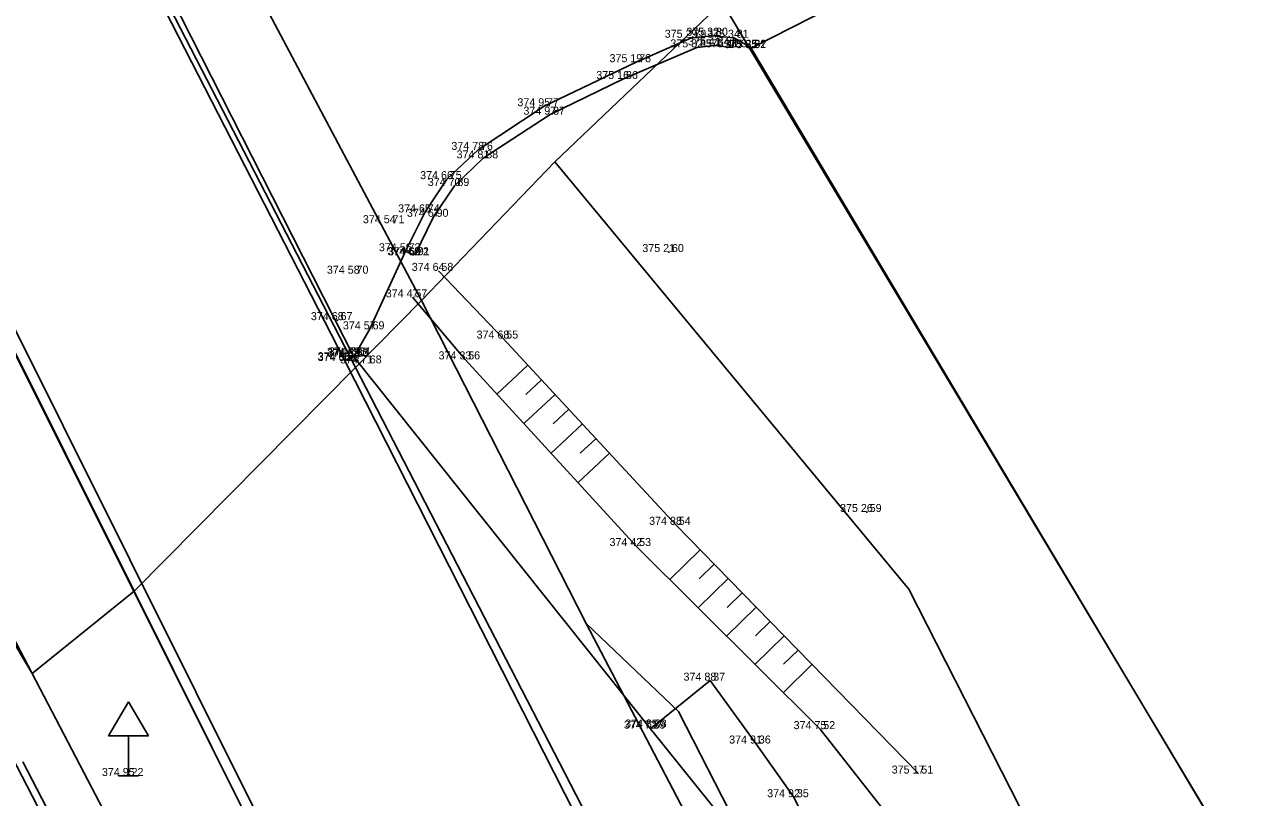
# Model space of a CAD drawing. Extents: x -601196 to -600262, y -1082523 to -1081922.
# Drawn here: x -600468.24 to -600437.88, y -1082336.09 to -1082316.78 of the extents above; entities that cross this region are included whole.
import ezdxf

# ---------------------------------------------------------------- set-up
doc = ezdxf.new("R2010")
doc.units = 0
for name, color, linetype in [('Vrstva 1', 7, 'Continuous'), ('Vrstva 10', 7, 'Continuous'), ('Vrstva 11', 7, 'Continuous'), ('Vrstva 14', 7, 'Continuous'), ('Vrstva 2', 7, 'Continuous'), ('Vrstva 20', 7, 'Continuous'), ('Vrstva 25', 7, 'Continuous'), ('Vrstva 3', 7, 'Continuous'), ('Vrstva 34', 7, 'Continuous'), ('Vrstva 47', 7, 'Continuous'), ('Vrstva 7', 7, 'Continuous')]:
    doc.layers.add(name, color=color, linetype=linetype)

msp = doc.modelspace()

# ---------------------------------------------------------------- linework, layer by layer
at = {"layer": 'Vrstva 1'}
for p, q in [((-600451.58, -1082317.12), (-600451.58, -1082317.12)), ((-600451.04, -1082317.07), (-600451.04, -1082317.07)), ((-600450.52, -1082317.12), (-600450.52, -1082317.12)), ((-600451.44, -1082317.36), (-600451.44, -1082317.36)), ((-600451, -1082317.31), (-600451, -1082317.31)), ((-600450.56, -1082317.36), (-600450.56, -1082317.36)), ((-600450.09, -1082317.38), (-600450.09, -1082317.38)), ((-600450.08, -1082317.37), (-600450.08, -1082317.37)), ((-600452.96, -1082317.73), (-600452.96, -1082317.73)), ((-600453.29, -1082318.15), (-600453.29, -1082318.15)), ((-600455.26, -1082318.83), (-600455.26, -1082318.83)), ((-600455.11, -1082319.04), (-600455.11, -1082319.04)), ((-600456.91, -1082319.92), (-600456.91, -1082319.92)), ((-600456.78, -1082320.13), (-600456.78, -1082320.13)), ((-600457.69, -1082320.65), (-600457.69, -1082320.65)), ((-600457.5, -1082320.82), (-600457.5, -1082320.82)), ((-600458.24, -1082321.48), (-600458.24, -1082321.48)), ((-600459.12, -1082321.75), (-600459.12, -1082321.75)), ((-600458.02, -1082321.59), (-600458.02, -1082321.59)), ((-600458.72, -1082322.45), (-600458.72, -1082322.45)), ((-600458.51, -1082322.55), (-600458.51, -1082322.55)), ((-600458.49, -1082322.55), (-600458.49, -1082322.55)), ((-600452.14, -1082322.47), (-600452.14, -1082322.47)), ((-600457.9, -1082322.94), (-600457.9, -1082322.94)), ((-600460.02, -1082323.01), (-600460.02, -1082323.01)), ((-600458.55, -1082323.6), (-600458.55, -1082323.6)), ((-600460.42, -1082324.17), (-600460.42, -1082324.17)), ((-600459.62, -1082324.4), (-600459.62, -1082324.4)), ((-600456.28, -1082324.63), (-600456.28, -1082324.63)), ((-600460.02, -1082325.06), (-600460.02, -1082325.06)), ((-600460.01, -1082325.09), (-600460.01, -1082325.09)), ((-600459.97, -1082325.05), (-600459.97, -1082325.05)), ((-600460.25, -1082325.17), (-600460.25, -1082325.17)), ((-600460.25, -1082325.19), (-600460.25, -1082325.19)), ((-600459.69, -1082325.25), (-600459.69, -1082325.25)), ((-600457.23, -1082325.15), (-600457.23, -1082325.15)), ((-600447.2, -1082328.96), (-600447.2, -1082328.96)), ((-600451.97, -1082329.28), (-600451.97, -1082329.28)), ((-600452.96, -1082329.81), (-600452.96, -1082329.81)), ((-600451.11, -1082333.17), (-600451.11, -1082333.17)), ((-600452.6, -1082334.37), (-600452.6, -1082334.37)), ((-600452.57, -1082334.34), (-600452.57, -1082334.34)), ((-600448.36, -1082334.38), (-600448.36, -1082334.38)), ((-600449.97, -1082334.74), (-600449.97, -1082334.74)), ((-600465.64, -1082335.55), (-600465.64, -1082335.55)), ((-600445.91, -1082335.49), (-600445.91, -1082335.49)), ((-600449.02, -1082336.08), (-600449.02, -1082336.08))]:
    msp.add_line(p, q, dxfattribs=at)
at = {"layer": 'Vrstva 10'}
for p, q in [((-600460.01, -1082325.09), (-600465.44, -1082314.41)), ((-600461.09, -1082339.77), (-600472.22, -1082317.55)), ((-600452.6, -1082334.37), (-600460.01, -1082325.09)), ((-600451.11, -1082333.17), (-600452.6, -1082334.37)), ((-600449.97, -1082334.74), (-600451.11, -1082333.17)), ((-600450.73, -1082336.7), (-600452.6, -1082334.37)), ((-600449.02, -1082336.08), (-600449.97, -1082334.74)), ((-600448.04, -1082338.04), (-600449.02, -1082336.08))]:
    msp.add_line(p, q, dxfattribs=at)
at = {"layer": 'Vrstva 11'}
for p, q in [((-600460.25, -1082325.17), (-600465.7, -1082314.53)), ((-600452.96, -1082317.73), (-600451.58, -1082317.12)), ((-600452.96, -1082317.73), (-600451.58, -1082317.12)), ((-600451.58, -1082317.12), (-600451.04, -1082317.07)), ((-600451.58, -1082317.12), (-600451.04, -1082317.07)), ((-600451.04, -1082317.07), (-600450.52, -1082317.12)), ((-600451.04, -1082317.07), (-600450.52, -1082317.12)), ((-600450.52, -1082317.12), (-600450.56, -1082317.36)), ((-600450.52, -1082317.12), (-600450.08, -1082317.37)), ((-600460.84, -1082339.7), (-600471.95, -1082317.45)), ((-600451.44, -1082317.36), (-600453.29, -1082318.15)), ((-600451, -1082317.31), (-600451.44, -1082317.36)), ((-600450.56, -1082317.36), (-600451, -1082317.31)), ((-600455.26, -1082318.83), (-600452.96, -1082317.73)), ((-600455.26, -1082318.83), (-600452.96, -1082317.73)), ((-600453.29, -1082318.15), (-600455.11, -1082319.04)), ((-600456.91, -1082319.92), (-600455.26, -1082318.83)), ((-600456.91, -1082319.92), (-600455.26, -1082318.83)), ((-600455.11, -1082319.04), (-600456.78, -1082320.13)), ((-600457.69, -1082320.65), (-600456.91, -1082319.92)), ((-600457.69, -1082320.65), (-600456.91, -1082319.92)), ((-600456.78, -1082320.13), (-600457.5, -1082320.82)), ((-600458.24, -1082321.48), (-600457.69, -1082320.65)), ((-600457.5, -1082320.82), (-600458.02, -1082321.59)), ((-600458.72, -1082322.45), (-600458.24, -1082321.48)), ((-600458.02, -1082321.59), (-600458.49, -1082322.55)), ((-600459.62, -1082324.4), (-600458.72, -1082322.45)), ((-600458.51, -1082322.55), (-600458.72, -1082322.45)), ((-600460.01, -1082325.09), (-600459.62, -1082324.4)), ((-600460.01, -1082325.09), (-600460.25, -1082325.17)), ((-600454.48, -1082336.5), (-600460.25, -1082325.17))]:
    msp.add_line(p, q, dxfattribs=at)
at = {"layer": 'Vrstva 14'}
for p, q in [((-600456.28, -1082324.63), (-600457.9, -1082322.94)), ((-600457.23, -1082325.15), (-600458.55, -1082323.6)), ((-600451.97, -1082329.28), (-600456.28, -1082324.63)), ((-600452.96, -1082329.81), (-600457.23, -1082325.15)), ((-600445.91, -1082335.49), (-600451.97, -1082329.28)), ((-600448.36, -1082334.38), (-600452.96, -1082329.81)), ((-600448.36, -1082334.38), (-600446.2, -1082337.13))]:
    msp.add_line(p, q, dxfattribs=at)
at = {"layer": 'Vrstva 20'}
for p, q in [((-600452.15, -1082322.47), (-600452.13, -1082322.47)), ((-600452.14, -1082322.455), (-600452.14, -1082322.47)), ((-600452.14, -1082322.485), (-600452.14, -1082322.47)), ((-600460.43, -1082324.17), (-600460.41, -1082324.17)), ((-600460.42, -1082324.155), (-600460.42, -1082324.17)), ((-600460.42, -1082324.185), (-600460.42, -1082324.17)), ((-600459.98, -1082325.05), (-600459.96, -1082325.05)), ((-600459.97, -1082325.035), (-600459.97, -1082325.05)), ((-600459.97, -1082325.065), (-600459.97, -1082325.05)), ((-600447.21, -1082328.96), (-600447.19, -1082328.96)), ((-600447.2, -1082328.945), (-600447.2, -1082328.96)), ((-600447.2, -1082328.975), (-600447.2, -1082328.96)), ((-600452.58, -1082334.34), (-600452.56, -1082334.34)), ((-600452.57, -1082334.325), (-600452.57, -1082334.34)), ((-600452.57, -1082334.355), (-600452.57, -1082334.34))]:
    msp.add_line(p, q, dxfattribs=at)
at = {"layer": 'Vrstva 25'}
for p, q in [((-600455.663, -1082325.296), (-600456.438, -1082326.014)), ((-600455.323, -1082325.662), (-600455.712, -1082326.023)), ((-600454.983, -1082326.029), (-600455.763, -1082326.751)), ((-600454.644, -1082326.396), (-600455.034, -1082326.758)), ((-600454.304, -1082326.762), (-600455.087, -1082327.488)), ((-600453.964, -1082327.129), (-600454.357, -1082327.493)), ((-600453.624, -1082327.495), (-600454.412, -1082328.225)), ((-600451.359, -1082329.906), (-600452.118, -1082330.647)), ((-600451.01, -1082330.264), (-600451.386, -1082330.632)), ((-600450.661, -1082330.622), (-600451.408, -1082331.351)), ((-600450.312, -1082330.979), (-600450.683, -1082331.342)), ((-600449.963, -1082331.337), (-600450.699, -1082332.056)), ((-600449.614, -1082331.695), (-600449.979, -1082332.051)), ((-600449.265, -1082332.052), (-600449.99, -1082332.76)), ((-600448.916, -1082332.41), (-600449.276, -1082332.761)), ((-600448.567, -1082332.768), (-600449.281, -1082333.465))]:
    msp.add_line(p, q, dxfattribs=at)
at = {"layer": 'Vrstva 34'}
for p, q in [((-600466.14, -1082334.55), (-600465.64, -1082333.7)), ((-600465.64, -1082333.7), (-600465.14, -1082334.55)), ((-600466.14, -1082334.55), (-600465.14, -1082334.55)), ((-600465.64, -1082335.55), (-600465.64, -1082334.55)), ((-600465.89, -1082335.55), (-600465.39, -1082335.55))]:
    msp.add_line(p, q, dxfattribs=at)
at = {"layer": 'Vrstva 47'}
for p, q in [((-600458.32, -1082323.68), (-600470.25, -1082301.21)), ((-600459.97, -1082325.35), (-600469.74, -1082306.44)), ((-600468.05, -1082332.99), (-600480.72, -1082308.79)), ((-600458.72, -1082354.01), (-600480.28, -1082312.49)), ((-600468.05, -1082332.99), (-600478.37, -1082315.69)), ((-600450.81, -1082316.24), (-600454.99, -1082320.22)), ((-600431.3, -1082348.8), (-600450.81, -1082316.24)), ((-600454.99, -1082320.22), (-600458.32, -1082323.68)), ((-600446.15, -1082330.89), (-600454.99, -1082320.22)), ((-600469.24, -1082323.45), (-600465.5, -1082330.94)), ((-600459.97, -1082325.35), (-600458.32, -1082323.68)), ((-600458.32, -1082323.68), (-600454.21, -1082331.74)), ((-600465.5, -1082330.94), (-600459.97, -1082325.35)), ((-600437.73, -1082368.41), (-600459.97, -1082325.35)), ((-600437.46, -1082347.91), (-600446.15, -1082330.89)), ((-600468.05, -1082332.99), (-600465.5, -1082330.94)), ((-600465.5, -1082330.94), (-600461.14, -1082339.69)), ((-600454.21, -1082331.74), (-600451.9, -1082333.94)), ((-600441.24, -1082356.52), (-600454.21, -1082331.74)), ((-600468.05, -1082332.99), (-600458.75, -1082350.75)), ((-600451.9, -1082333.94), (-600443.25, -1082350.86)), ((-600460.9, -1082349.46), (-600468.28, -1082335.2))]:
    msp.add_line(p, q, dxfattribs=at)
at = {"layer": 'Vrstva 7'}
for p, q in [((-600450.09, -1082317.38), (-600440.33, -1082312.41)), ((-600431.39, -1082348.72), (-600450.09, -1082317.38))]:
    msp.add_line(p, q, dxfattribs=at)

# ---------------------------------------------------------------- texts
at = {"layer": 'Vrstva 2'}
for s, p in [(' 79', (-600451.58, -1082317.12)), (' 80', (-600451.04, -1082317.07)), (' 81', (-600450.52, -1082317.12)), (' 85', (-600451.44, -1082317.36)), (' 84', (-600451, -1082317.31)), (' 83', (-600450.56, -1082317.36)), (' 61', (-600450.09, -1082317.38)), (' 82', (-600450.08, -1082317.37)), (' 78', (-600452.96, -1082317.73)), (' 86', (-600453.29, -1082318.15)), (' 77', (-600455.26, -1082318.83)), (' 87', (-600455.11, -1082319.04)), (' 76', (-600456.91, -1082319.92)), (' 88', (-600456.78, -1082320.13)), (' 75', (-600457.69, -1082320.65)), (' 89', (-600457.5, -1082320.82)), (' 74', (-600458.24, -1082321.48)), (' 90', (-600458.02, -1082321.59)), (' 71', (-600459.12, -1082321.75)), (' 73', (-600458.72, -1082322.45)), (' 72', (-600458.51, -1082322.55)), (' 91', (-600458.49, -1082322.55)), (' 60', (-600452.14, -1082322.47)), (' 70', (-600460.02, -1082323.01)), (' 58', (-600457.9, -1082322.94)), (' 57', (-600458.55, -1082323.6)), (' 67', (-600460.42, -1082324.17)), (' 69', (-600459.62, -1082324.4)), (' 55', (-600456.28, -1082324.63)), (' 66', (-600460.25, -1082325.17)), (' 62', (-600460.25, -1082325.19)), (' 65', (-600460.02, -1082325.06)), (' 63', (-600460.01, -1082325.09)), (' 64', (-600459.97, -1082325.05)), (' 68', (-600459.69, -1082325.25)), (' 56', (-600457.23, -1082325.15)), (' 59', (-600447.2, -1082328.96)), (' 54', (-600451.97, -1082329.28)), (' 53', (-600452.96, -1082329.81)), (' 37', (-600451.11, -1082333.17)), (' 39', (-600452.6, -1082334.37)), (' 38', (-600452.57, -1082334.34)), (' 52', (-600448.36, -1082334.38)), (' 36', (-600449.97, -1082334.74)), (' 22', (-600465.64, -1082335.55)), (' 51', (-600445.91, -1082335.49)), (' 35', (-600449.02, -1082336.08))]:
    msp.add_text(s, height=0.2, dxfattribs=at).set_placement(p)
at = {"layer": 'Vrstva 3'}
for s, p in [('375 29 ', (-600452.246, -1082317.12)), ('375 32 ', (-600451.706, -1082317.07)), ('375 34 ', (-600451.186, -1082317.12)), ('375 32 ', (-600452.106, -1082317.36)), ('375 41 ', (-600451.666, -1082317.31)), ('375 41 ', (-600451.226, -1082317.36)), ('375 35 ', (-600450.756, -1082317.38)), ('375 35 ', (-600450.746, -1082317.37)), ('375 19 ', (-600453.626, -1082317.73)), ('375 16 ', (-600453.956, -1082318.15)), ('374 95 ', (-600455.926, -1082318.83)), ('374 97 ', (-600455.776, -1082319.04)), ('374 78 ', (-600457.576, -1082319.92)), ('374 81 ', (-600457.446, -1082320.13)), ('374 66 ', (-600458.356, -1082320.65)), ('374 70 ', (-600458.166, -1082320.82)), ('374 65 ', (-600458.906, -1082321.48)), ('374 67 ', (-600458.686, -1082321.59)), ('374 54 ', (-600459.786, -1082321.75)), ('374 56 ', (-600459.386, -1082322.45)), ('374 60 ', (-600459.176, -1082322.55)), ('374 62 ', (-600459.156, -1082322.55)), ('375 21 ', (-600452.806, -1082322.47)), ('374 58 ', (-600460.686, -1082323.01)), ('374 64 ', (-600458.566, -1082322.94)), ('374 47 ', (-600459.216, -1082323.6)), ('374 68 ', (-600461.086, -1082324.17)), ('374 57 ', (-600460.286, -1082324.4)), ('374 68 ', (-600456.946, -1082324.63)), ('374 65 ', (-600460.916, -1082325.17)), ('374 66 ', (-600460.916, -1082325.19)), ('374 65 ', (-600460.686, -1082325.06)), ('374 63 ', (-600460.676, -1082325.09)), ('374 77 ', (-600460.636, -1082325.05)), ('374 71 ', (-600460.356, -1082325.25)), ('374 33 ', (-600457.896, -1082325.15)), ('375 26 ', (-600447.866, -1082328.96)), ('374 88 ', (-600452.636, -1082329.28)), ('374 42 ', (-600453.626, -1082329.81)), ('374 88 ', (-600451.776, -1082333.17)), ('374 72 ', (-600453.266, -1082334.37)), ('374 85 ', (-600453.236, -1082334.34)), ('374 75 ', (-600449.026, -1082334.38)), ('374 91 ', (-600450.636, -1082334.74)), ('374 95 ', (-600466.306, -1082335.55)), ('375 17 ', (-600446.576, -1082335.49)), ('374 92 ', (-600449.686, -1082336.08))]:
    msp.add_text(s, height=0.2, dxfattribs=at).set_placement(p)

doc.saveas('drawing.dxf')
